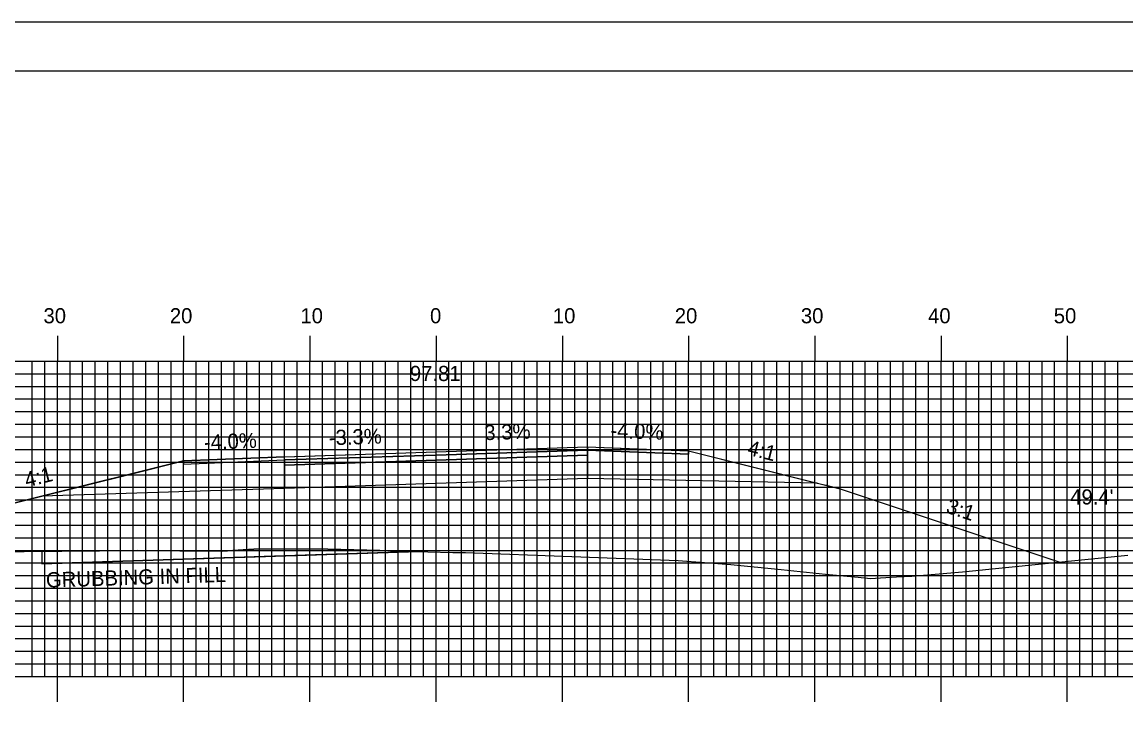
# Model space of a CAD drawing. Extents: x 1763365 to 1763708, y 442591 to 442811.
# Drawn here: x 1763498 to 1763585.5, y 442756.2 to 442810.5 of the extents above; entities that cross this region are included whole.
import ezdxf

# ---------------------------------------------------------------- set-up
doc = ezdxf.new("R2010")
doc.units = 0
for name, color, linetype in [('ANNOTATION', 7, 'Continuous'), ('BORDER', 7, 'Continuous'), ('D_Roadway_Centerline', 7, 'Continuous'), ('D_Roadway_Centerline_Text', 7, 'Continuous'), ('D_Roadway_Edge_Shoulder', 7, 'Continuous'), ('D_Roadway_Edge_TW', 7, 'Continuous'), ('D_Roadway_Pavement', 7, 'Continuous'), ('D_Roadway_SlopeLines', 7, 'Continuous'), ('D_Roadway_SubGrade', 7, 'Continuous'), ('D_Text_Standard', 7, 'Continuous'), ('GRUBBING IN FILL', 7, 'Continuous'), ('H_V ANNOTATION', 7, 'Continuous'), ('MAJOR', 7, 'Continuous'), ('MINOR', 7, 'Continuous'), ('PLOT BOUNDARY', 7, 'Continuous'), ('S_Roadway_Centerline', 7, 'Continuous')]:
    doc.layers.add(name, color=color, linetype=linetype)

msp = doc.modelspace()

# ---------------------------------------------------------------- linework, layer by layer
at = {"layer": 'BORDER'}
msp.add_lwpolyline([(1763381.205, 442596.665), (1763701.205, 442596.665), (1763701.205, 442806.665), (1763381.205, 442806.665)], close=True, dxfattribs=at)
at = {"layer": 'D_Roadway_Centerline'}
msp.add_lwpolyline([(1763482.748, 442768.746), (1763482.753, 442768.747), (1763499.569, 442772.951), (1763499.576, 442772.953), (1763506.374, 442774.652), (1763510.802, 442775.759), (1763510.805, 442775.76), (1763518.799, 442776.08), (1763518.805, 442776.08), (1763518.815, 442776.081), (1763530.806, 442776.473), (1763530.81, 442776.473), (1763542.806, 442776.865), (1763542.809, 442776.865), (1763546.668, 442776.711), (1763550.805, 442776.545), (1763557.356, 442774.908), (1763560.98, 442774.002), (1763561.702, 442773.821), (1763562.805, 442773.545), (1763562.812, 442773.543), (1763580.229, 442767.738)], dxfattribs=at)
at = {"layer": 'D_Roadway_Edge_Shoulder'}
for points in [[(1763542.806, 442776.865), (1763550.805, 442776.545), (1763550.805, 442776.295), (1763542.806, 442776.615)], [(1763518.805, 442776.08), (1763510.805, 442775.76), (1763510.805, 442775.51), (1763518.805, 442775.83)]]:
    msp.add_lwpolyline(points, close=True, dxfattribs=at)
at = {"layer": 'D_Roadway_Edge_TW'}
for points in [[(1763518.805, 442775.83), (1763518.805, 442776.08), (1763530.806, 442776.473), (1763542.806, 442776.865), (1763542.806, 442776.615), (1763530.806, 442776.223)], [(1763542.806, 442776.865), (1763542.806, 442776.865), (1763542.806, 442776.615), (1763542.806, 442776.615)]]:
    msp.add_lwpolyline(points, close=True, dxfattribs=at)
at = {"layer": 'D_Roadway_Pavement'}
for points in [[(1763518.805, 442775.414), (1763518.805, 442775.83), (1763530.806, 442776.223), (1763542.806, 442776.615), (1763542.806, 442776.199), (1763530.806, 442775.806)], [(1763542.806, 442776.615), (1763542.806, 442776.615), (1763542.806, 442776.199), (1763542.806, 442776.199)]]:
    msp.add_lwpolyline(points, close=True, dxfattribs=at)
msp.add_lwpolyline([(1763542.806, 442776.615), (1763542.806, 442776.199)], dxfattribs=at)
msp.add_lwpolyline([(1763542.806, 442776.615), (1763542.806, 442776.199)], dxfattribs=at)
msp.add_lwpolyline([(1763542.806, 442776.615), (1763542.806, 442776.199)], dxfattribs=at)
at = {"layer": 'D_Roadway_SlopeLines'}
for points in [[(1763550.805, 442776.545), (1763562.805, 442773.545), (1763580.229, 442767.738)], [(1763510.805, 442775.76), (1763499.569, 442772.951), (1763482.748, 442768.746)]]:
    msp.add_lwpolyline(points, dxfattribs=at)
at = {"layer": 'D_Roadway_SubGrade'}
for points in [[(1763542.806, 442776.199), (1763542.806, 442776.615), (1763550.805, 442776.295), (1763550.805, 442776.545), (1763560.98, 442774.002), (1763542.806, 442774.365)], [(1763510.805, 442775.51), (1763518.805, 442775.83), (1763518.805, 442775.414), (1763518.805, 442773.58), (1763499.569, 442772.951), (1763510.805, 442775.76)], [(1763518.805, 442773.58), (1763518.805, 442775.414), (1763530.806, 442775.806), (1763542.806, 442776.199), (1763542.806, 442774.365), (1763530.806, 442773.973)], [(1763542.806, 442776.199), (1763542.806, 442776.199), (1763542.806, 442774.365), (1763542.806, 442774.365)]]:
    msp.add_lwpolyline(points, close=True, dxfattribs=at)
at = {"layer": 'GRUBBING IN FILL'}
for q in [(1763499.569, 442768.091), (1763499.569, 442767.591), (1763499.569, 442767.591)]:
    msp.add_line((1763499.569, 442768.591), q, dxfattribs=at)
msp.add_lwpolyline([(1763499.569, 442768.591), (1763499.569, 442767.591), (1763509.187, 442767.906), (1763529.438, 442768.568), (1763522.227, 442768.75), (1763519.512, 442768.769), (1763516.797, 442768.788), (1763513.867, 442768.608), (1763510.502, 442768.637), (1763507.136, 442768.666), (1763501.144, 442768.607)], close=True, dxfattribs=at)
msp.add_lwpolyline([(1763499.569, 442768.591), (1763499.569, 442767.591), (1763509.187, 442767.906), (1763529.438, 442768.568), (1763522.227, 442768.75), (1763519.512, 442768.769), (1763516.797, 442768.788), (1763513.867, 442768.608), (1763510.502, 442768.637), (1763507.136, 442768.666), (1763501.144, 442768.607)], close=True, dxfattribs=at)
msp.add_lwpolyline([(1763529.438, 442768.568), (1763518.805, 442768.22), (1763499.569, 442767.591)], dxfattribs=at)
at = {"layer": 'MAJOR'}
for p, q in [((1763500.805, 442785.669), (1763500.805, 442783.665)), ((1763510.805, 442785.669), (1763510.805, 442783.665)), ((1763520.805, 442785.669), (1763520.805, 442783.665)), ((1763530.805, 442785.669), (1763530.805, 442783.665)), ((1763540.805, 442785.669), (1763540.805, 442783.665)), ((1763550.805, 442785.669), (1763550.805, 442783.665)), ((1763560.805, 442785.669), (1763560.805, 442783.665)), ((1763570.805, 442785.669), (1763570.805, 442783.665)), ((1763580.805, 442785.669), (1763580.805, 442783.665)), ((1763390.805, 442783.665), (1763670.805, 442783.665)), ((1763390.805, 442783.665), (1763670.805, 442783.665)), ((1763500.805, 442758.665), (1763500.805, 442783.665)), ((1763510.805, 442758.665), (1763510.805, 442783.665)), ((1763520.805, 442758.665), (1763520.805, 442783.665)), ((1763530.805, 442758.665), (1763530.805, 442783.665)), ((1763540.805, 442758.665), (1763540.805, 442783.665)), ((1763550.805, 442758.665), (1763550.805, 442783.665)), ((1763560.805, 442758.665), (1763560.805, 442783.665)), ((1763570.805, 442758.665), (1763570.805, 442783.665)), ((1763580.805, 442758.665), (1763580.805, 442783.665)), ((1763390.805, 442778.665), (1763670.805, 442778.665)), ((1763390.805, 442773.665), (1763670.805, 442773.665)), ((1763390.805, 442768.665), (1763670.805, 442768.665)), ((1763390.805, 442763.665), (1763670.805, 442763.665)), ((1763390.805, 442758.665), (1763670.805, 442758.665)), ((1763390.805, 442758.665), (1763670.805, 442758.665)), ((1763500.805, 442756.661), (1763500.805, 442758.665)), ((1763510.805, 442756.661), (1763510.805, 442758.665)), ((1763520.805, 442756.661), (1763520.805, 442758.665)), ((1763530.805, 442756.661), (1763530.805, 442758.665)), ((1763540.805, 442756.661), (1763540.805, 442758.665)), ((1763550.805, 442756.661), (1763550.805, 442758.665)), ((1763560.805, 442756.661), (1763560.805, 442758.665)), ((1763570.805, 442756.661), (1763570.805, 442758.665)), ((1763580.805, 442756.661), (1763580.805, 442758.665))]:
    msp.add_line(p, q, dxfattribs=at)
at = {"layer": 'MINOR'}
for p, q in [((1763498.805, 442758.665), (1763498.805, 442783.665)), ((1763499.805, 442758.665), (1763499.805, 442783.665)), ((1763501.805, 442758.665), (1763501.805, 442783.665)), ((1763502.805, 442758.665), (1763502.805, 442783.665)), ((1763503.805, 442758.665), (1763503.805, 442783.665)), ((1763504.805, 442758.665), (1763504.805, 442783.665)), ((1763505.805, 442758.665), (1763505.805, 442783.665)), ((1763506.805, 442758.665), (1763506.805, 442783.665)), ((1763507.805, 442758.665), (1763507.805, 442783.665)), ((1763508.805, 442758.665), (1763508.805, 442783.665)), ((1763509.805, 442758.665), (1763509.805, 442783.665)), ((1763511.805, 442758.665), (1763511.805, 442783.665)), ((1763512.805, 442758.665), (1763512.805, 442783.665)), ((1763513.805, 442758.665), (1763513.805, 442783.665)), ((1763514.805, 442758.665), (1763514.805, 442783.665)), ((1763515.805, 442758.665), (1763515.805, 442783.665)), ((1763516.805, 442758.665), (1763516.805, 442783.665)), ((1763517.805, 442758.665), (1763517.805, 442783.665)), ((1763518.805, 442758.665), (1763518.805, 442783.665)), ((1763519.805, 442758.665), (1763519.805, 442783.665)), ((1763521.805, 442758.665), (1763521.805, 442783.665)), ((1763522.805, 442758.665), (1763522.805, 442783.665)), ((1763523.805, 442758.665), (1763523.805, 442783.665)), ((1763524.805, 442758.665), (1763524.805, 442783.665)), ((1763525.805, 442758.665), (1763525.805, 442783.665)), ((1763526.805, 442758.665), (1763526.805, 442783.665)), ((1763527.805, 442758.665), (1763527.805, 442783.665)), ((1763528.805, 442758.665), (1763528.805, 442783.665)), ((1763529.805, 442758.665), (1763529.805, 442783.665)), ((1763531.805, 442758.665), (1763531.805, 442783.665)), ((1763532.805, 442758.665), (1763532.805, 442783.665)), ((1763533.805, 442758.665), (1763533.805, 442783.665)), ((1763534.805, 442758.665), (1763534.805, 442783.665)), ((1763535.805, 442758.665), (1763535.805, 442783.665)), ((1763536.805, 442758.665), (1763536.805, 442783.665)), ((1763537.805, 442758.665), (1763537.805, 442783.665)), ((1763538.805, 442758.665), (1763538.805, 442783.665)), ((1763539.805, 442758.665), (1763539.805, 442783.665)), ((1763541.805, 442758.665), (1763541.805, 442783.665)), ((1763542.805, 442758.665), (1763542.805, 442783.665)), ((1763543.805, 442758.665), (1763543.805, 442783.665)), ((1763544.805, 442758.665), (1763544.805, 442783.665)), ((1763545.805, 442758.665), (1763545.805, 442783.665)), ((1763546.805, 442758.665), (1763546.805, 442783.665)), ((1763547.805, 442758.665), (1763547.805, 442783.665)), ((1763548.805, 442758.665), (1763548.805, 442783.665)), ((1763549.805, 442758.665), (1763549.805, 442783.665)), ((1763551.805, 442758.665), (1763551.805, 442783.665)), ((1763552.805, 442758.665), (1763552.805, 442783.665)), ((1763553.805, 442758.665), (1763553.805, 442783.665)), ((1763554.805, 442758.665), (1763554.805, 442783.665)), ((1763555.805, 442758.665), (1763555.805, 442783.665)), ((1763556.805, 442758.665), (1763556.805, 442783.665)), ((1763557.805, 442758.665), (1763557.805, 442783.665)), ((1763558.805, 442758.665), (1763558.805, 442783.665)), ((1763559.805, 442758.665), (1763559.805, 442783.665)), ((1763561.805, 442758.665), (1763561.805, 442783.665)), ((1763562.805, 442758.665), (1763562.805, 442783.665)), ((1763563.805, 442758.665), (1763563.805, 442783.665)), ((1763564.805, 442758.665), (1763564.805, 442783.665)), ((1763565.805, 442758.665), (1763565.805, 442783.665)), ((1763566.805, 442758.665), (1763566.805, 442783.665)), ((1763567.805, 442758.665), (1763567.805, 442783.665)), ((1763568.805, 442758.665), (1763568.805, 442783.665)), ((1763569.805, 442758.665), (1763569.805, 442783.665)), ((1763571.805, 442758.665), (1763571.805, 442783.665)), ((1763572.805, 442758.665), (1763572.805, 442783.665)), ((1763573.805, 442758.665), (1763573.805, 442783.665)), ((1763574.805, 442758.665), (1763574.805, 442783.665)), ((1763575.805, 442758.665), (1763575.805, 442783.665)), ((1763576.805, 442758.665), (1763576.805, 442783.665)), ((1763577.805, 442758.665), (1763577.805, 442783.665)), ((1763578.805, 442758.665), (1763578.805, 442783.665)), ((1763579.805, 442758.665), (1763579.805, 442783.665)), ((1763581.805, 442758.665), (1763581.805, 442783.665)), ((1763582.805, 442758.665), (1763582.805, 442783.665)), ((1763583.805, 442758.665), (1763583.805, 442783.665)), ((1763584.805, 442758.665), (1763584.805, 442783.665)), ((1763390.805, 442782.665), (1763670.805, 442782.665)), ((1763390.805, 442781.665), (1763670.805, 442781.665)), ((1763390.805, 442780.665), (1763670.805, 442780.665)), ((1763390.805, 442779.665), (1763670.805, 442779.665)), ((1763390.805, 442777.665), (1763670.805, 442777.665)), ((1763390.805, 442776.665), (1763670.805, 442776.665)), ((1763390.805, 442775.665), (1763670.805, 442775.665)), ((1763390.805, 442774.665), (1763670.805, 442774.665)), ((1763390.805, 442772.665), (1763670.805, 442772.665)), ((1763390.805, 442771.665), (1763670.805, 442771.665)), ((1763390.805, 442770.665), (1763670.805, 442770.665)), ((1763390.805, 442769.665), (1763670.805, 442769.665)), ((1763390.805, 442767.665), (1763670.805, 442767.665)), ((1763390.805, 442766.665), (1763670.805, 442766.665)), ((1763390.805, 442765.665), (1763670.805, 442765.665)), ((1763390.805, 442764.665), (1763670.805, 442764.665)), ((1763390.805, 442762.665), (1763670.805, 442762.665)), ((1763390.805, 442761.665), (1763670.805, 442761.665)), ((1763390.805, 442760.665), (1763670.805, 442760.665)), ((1763390.805, 442759.665), (1763670.805, 442759.665))]:
    msp.add_line(p, q, dxfattribs=at)
at = {"layer": 'PLOT BOUNDARY'}
msp.add_lwpolyline([(1763365.019, 442590.547), (1763705.019, 442590.547), (1763705.019, 442810.547), (1763365.019, 442810.547)], close=True, dxfattribs=at)
at = {"layer": 'S_Roadway_Centerline'}
msp.add_lwpolyline([(1763495.151, 442768.547), (1763507.136, 442768.666), (1763513.867, 442768.608), (1763516.797, 442768.788), (1763522.227, 442768.75), (1763532.13, 442768.5), (1763532.387, 442768.501), (1763533.123, 442768.499), (1763549.969, 442767.854), (1763554.143, 442767.539), (1763558.148, 442767.137), (1763561.662, 442766.787), (1763564.242, 442766.54), (1763565.209, 442766.435), (1763566.005, 442766.482), (1763567.29, 442766.557), (1763567.887, 442766.592), (1763568.244, 442766.612), (1763568.495, 442766.626), (1763572.497, 442766.969), (1763585.608, 442768.272)], dxfattribs=at)

# ---------------------------------------------------------------- texts
at = {"layer": 'ANNOTATION'}
for s, rotation, p in [('-3.3%', 1.87567, (1763522.328, 442776.997)), ('3.3%', 1.87105, (1763534.646, 442777.4)), ('-4.0%', 357.70928, (1763544.599, 442777.595)), ('-4.0%', 2.29063, (1763512.434, 442776.627)), ('4:1', 345.96672, (1763555.398, 442776.259)), ('4:1', 14.03589, (1763498.37, 442773.646)), ('3:1', 341.56827, (1763571.124, 442771.681))]:
    msp.add_text(s, height=1.2, rotation=rotation, dxfattribs=at).set_placement(p)
at = {"layer": 'D_Roadway_Centerline'}
for s, p in [('C', (1763530.801, 442776.473)), ('L', (1763530.806, 442776.466))]:
    msp.add_text(s, height=0.0146, dxfattribs=at).set_placement(p)
at = {"layer": 'D_Roadway_Centerline_Text'}
msp.add_text('97.81', height=1.2, dxfattribs=at).set_placement((1763528.729, 442782.089))
at = {"layer": 'D_Text_Standard'}
msp.add_text("49.4'", height=1.2, dxfattribs=at).set_placement((1763581.039, 442772.3))
at = {"layer": 'GRUBBING IN FILL'}
msp.add_text('GRUBBING IN FILL', height=1.2, rotation=1.82025, dxfattribs=at).set_placement((1763499.917, 442765.712))
at = {"layer": 'H_V ANNOTATION'}
for s, p in [('30', (1763499.703, 442786.665)), ('20', (1763509.713, 442786.665)), ('10', (1763520.056, 442786.665)), ('0', (1763530.324, 442786.665)), ('10', (1763540.056, 442786.665)), ('20', (1763549.713, 442786.665)), ('30', (1763559.703, 442786.665)), ('40', (1763569.778, 442786.665)), ('50', (1763579.735, 442786.665))]:
    msp.add_text(s, height=1.2, dxfattribs=at).set_placement(p)

doc.saveas('drawing.dxf')
